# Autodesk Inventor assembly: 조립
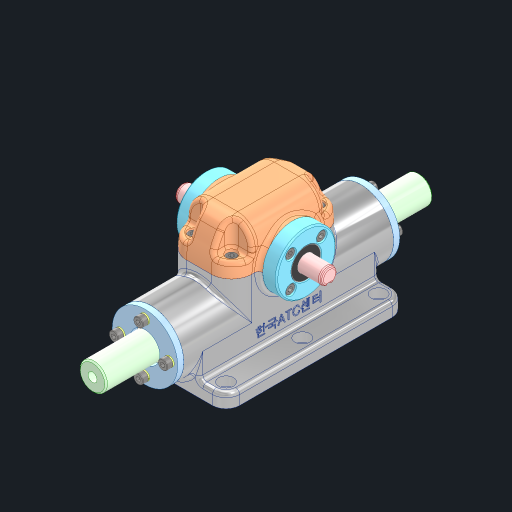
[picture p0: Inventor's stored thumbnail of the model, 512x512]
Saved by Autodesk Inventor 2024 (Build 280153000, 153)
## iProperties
Created: 2024-06
Part Number: 조립
Document SubType Name: Assembly
Designer: kh_501
Author: kh_501
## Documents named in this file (13)
- C:\Users\kh_501\Desktop\740604V1010\조립.iam
- C:\Users\kh_501\Desktop\740604V1010\본체.ipt
- C:\Users\kh_501\Desktop\740604V1010\깊은 홈 볼 베어링 6901\깊은 홈 볼 베어링 6901.ipt
- C:\Users\kh_501\Desktop\740604V1010\랙\랙.ipt
- C:\Users\kh_501\Desktop\740604V1010\베어링 커버\베어링 커버.ipt
- C:\Users\kh_501\Desktop\740604V1010\부시 커버\부시 커버.ipt
- C:\Users\kh_501\Desktop\740604V1010\스프링 와셔 M4\스프링 와셔 M4.ipt
- C:\Users\kh_501\Desktop\740604V1010\오일레스 부시\오일레스 부시.ipt
- C:\Users\kh_501\Desktop\740604V1010\오일실 12 22 7\오일실 12 22 7.ipt
- C:\Users\kh_501\Desktop\740604V1010\윗커버\윗커버.ipt
- C:\Users\kh_501\Desktop\740604V1010\육각 소켓 머리 볼트 M4x10\육각 소켓 머리 볼트 M4x10.ipt
- C:\Users\kh_501\Desktop\740604V1010\칼라\칼라.ipt
- C:\Users\kh_501\Desktop\740604V1010\피니언\피니언.ipt
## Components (1 placed, 1 different names)
1. 피니언:1 — 각도:8
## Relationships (1: Angle 1)
- 각도:8 [Angle]: 피니언:1
